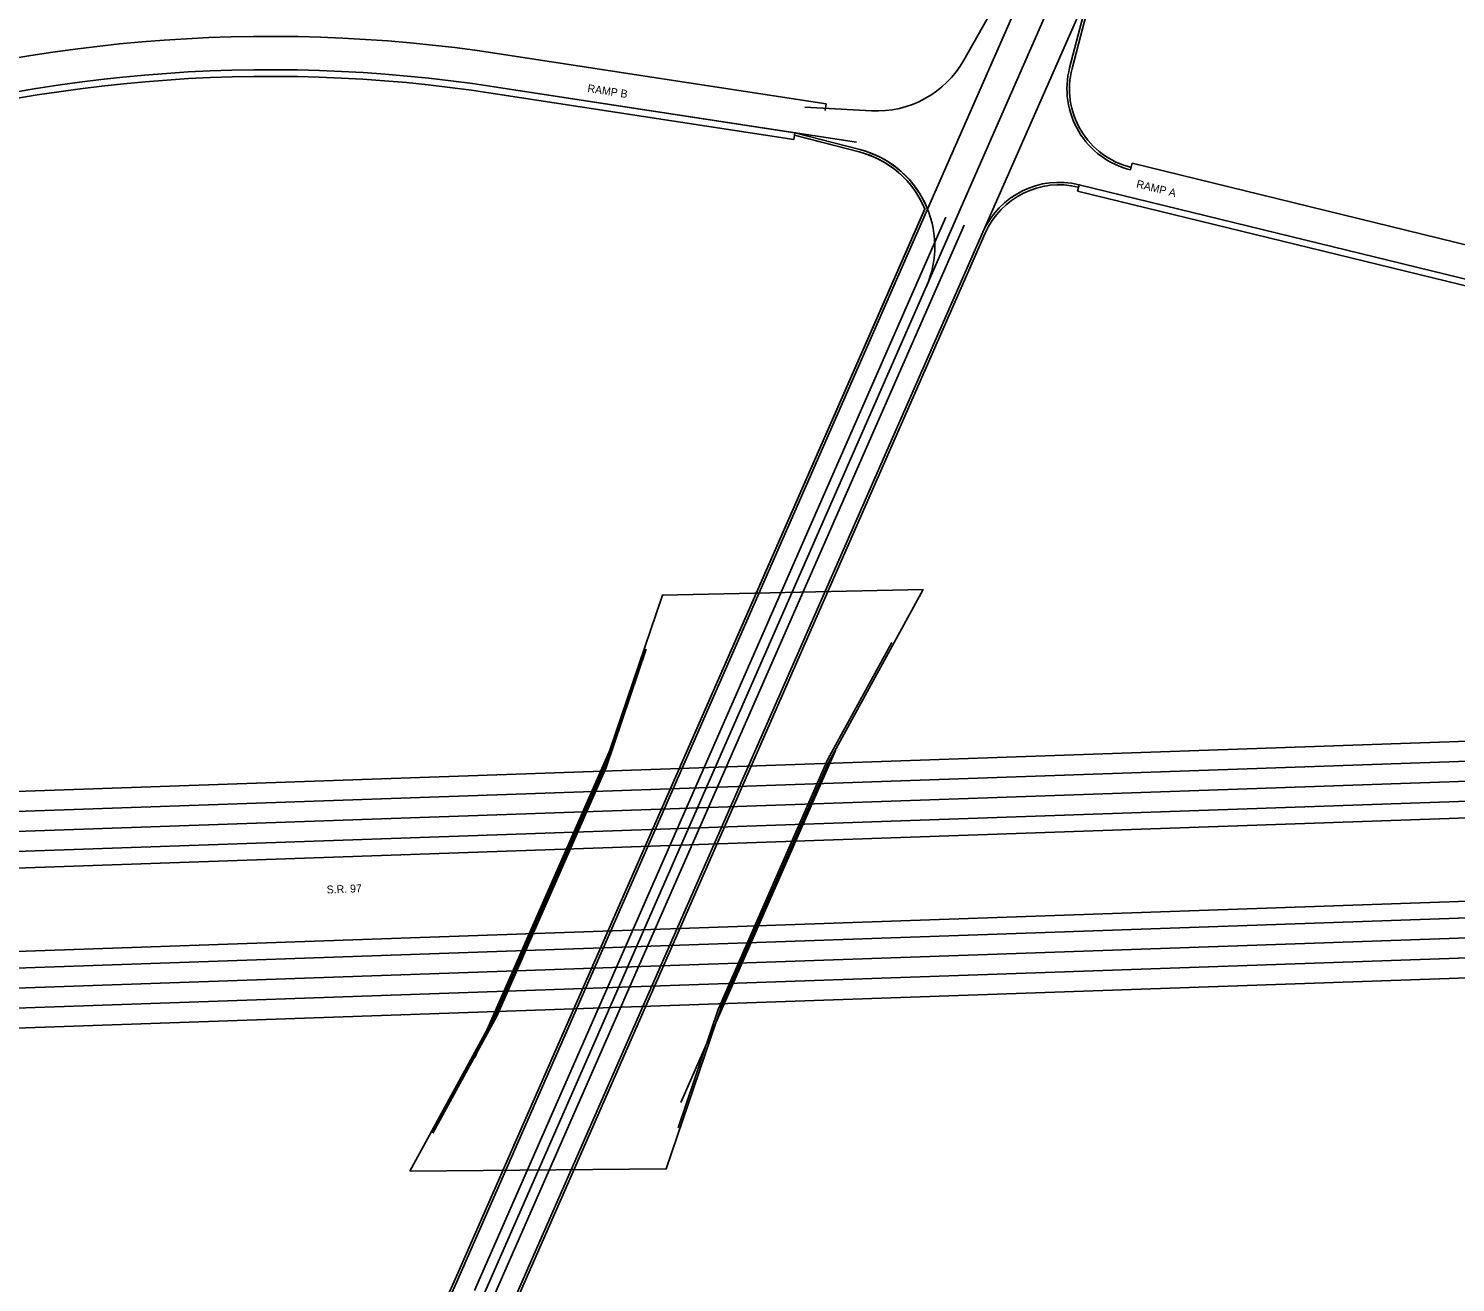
# Model space of a CAD drawing. Extents: x 2315515 to 2326910, y 758186 to 762794.
# Drawn here: x 2320623 to 2321480, y 759999 to 760752 of the extents above; entities that cross this region are included whole.
import ezdxf

# ---------------------------------------------------------------- set-up
doc = ezdxf.new("R2010")
doc.units = 0
for name, color, linetype in [('_CIVIL_CONSTRUCTION', 7, 'Continuous'), ('Bridge_Abutment', 7, 'Continuous'), ('Bridge_Bearing', 7, 'Continuous'), ('Bridge_Deck', 7, 'Continuous'), ('Clipping_Shape', 7, 'Continuous'), ('Default', 7, 'Continuous'), ('Draft_Corr_Design', 7, 'Continuous'), ('Draft_Corr_Range_Design', 7, 'Continuous'), ('E_Terrain_Exterior', 7, 'Continuous'), ('Pavement Marking Yellow', 7, 'Continuous'), ('Road_Curb_Face', 7, 'Continuous'), ('TL_Base Extension Sub', 7, 'Continuous'), ('TL_End Condition Ditch In', 7, 'Continuous'), ('TL_Pavement Centerline', 7, 'Continuous'), ('TL_Pavement Centerline Sub', 7, 'Continuous')]:
    doc.layers.add(name, color=color, linetype=linetype)

msp = doc.modelspace()

# ---------------------------------------------------------------- linework, layer by layer
at = {"layer": '_CIVIL_CONSTRUCTION'}
for p, q in [((2320276.47, 760246.31), (2324005.99, 760375.28)), ((2320278.89, 760176.35), (2324008.41, 760305.32))]:
    msp.add_line(p, q, dxfattribs=at)
at = {"layer": 'Bridge_Abutment'}
for p, q in [((2320969.99, 760308.48), (2320994.04, 760379.52)), ((2321103.18, 760313.34), (2321141.61, 760383.5)), ((2321037.24, 760163.18), (2321103.18, 760313.34)), ((2320904.45, 760159.23), (2320969.99, 760308.48)), ((2320866.02, 760089.07), (2320904.45, 760159.23)), ((2321013.19, 760092.14), (2321037.24, 760163.18))]:
    msp.add_line(p, q, dxfattribs=at)
at = {"layer": 'Bridge_Bearing'}
for p, q in [((2320994.04, 760379.52), (2320969.99, 760308.48)), ((2321141.61, 760383.5), (2321103.18, 760313.34)), ((2321037.24, 760163.18), (2321103.18, 760313.34)), ((2320904.45, 760159.23), (2320969.99, 760308.48)), ((2320866.02, 760089.07), (2320904.45, 760159.23)), ((2321013.19, 760092.14), (2321037.24, 760163.18))]:
    msp.add_line(p, q, dxfattribs=at)
at = {"layer": 'Bridge_Deck'}
for p, q in [((2320891.32, 760134.31), (2320977.73, 760331.08)), ((2321014.91, 760107.35), (2321107.69, 760318.64)), ((2321083.8, 760264.22), (2321104.32, 760310.96)), ((2320946.28, 760259.47), (2320966.81, 760306.21)), ((2320903.45, 760161.93), (2320923.97, 760208.67)), ((2321040.97, 760166.69), (2321061.49, 760213.42))]:
    msp.add_line(p, q, dxfattribs=at)
at = {"layer": 'Clipping_Shape'}
for p, q in [((2320969.05, 760308.84), (2320993.1, 760379.84)), ((2320903.55, 760159.68), (2320969.05, 760308.84)), ((2320865.15, 760089.55), (2320903.55, 760159.68))]:
    msp.add_line(p, q, dxfattribs=at)
msp.add_lwpolyline([(2320852.18, 760066.22), (2320904.32, 760161.43), (2320968.54, 760307.66), (2321003.83, 760411.9), (2321160.28, 760415.23), (2321103.45, 760311.46), (2321039.24, 760165.23), (2321006.16, 760067.57)], close=True, dxfattribs=at)
at = {"layer": 'Default'}
msp.add_line((2320896.62, 759992.18), (2321353.37, 761032.31), dxfattribs=at)
msp.add_line((2320896.62, 759992.18), (2321353.37, 761032.31), dxfattribs=at)
msp.add_line((2320896.62, 759992.18), (2321353.37, 761032.31), dxfattribs=at)
at = {"layer": 'Draft_Corr_Design'}
for p, q in [((2320276.82, 760236.32), (2324006.34, 760365.29)), ((2320278.54, 760186.35), (2324008.07, 760315.32))]:
    msp.add_line(p, q, dxfattribs=at)
at = {"layer": 'Draft_Corr_Range_Design'}
for p, q in [((2320276.06, 760258.31), (2324005.58, 760387.27)), ((2320279.3, 760164.36), (2324008.83, 760293.33))]:
    msp.add_line(p, q, dxfattribs=at)
at = {"layer": 'E_Terrain_Exterior'}
for p, q in [((2321248.25, 760728.26), (2321261.03, 760777.26)), ((2321184.77, 760732.91), (2321204.51, 760767.93)), ((2320902.91, 760716.92), (2321120.26, 760683.63)), ((2320902.91, 760716.92), (2321083.3, 760689.29)), ((2321089.22, 760704.57), (2321129.36, 760702.47)), ((2321083.3, 760689.29), (2321122.24, 760679.28)), ((2321083.3, 760689.29), (2321122.24, 760679.28)), ((2321253.87, 760658.15), (2322014.36, 760472.45)), ((2321253.87, 760658.15), (2322014.36, 760472.45)), ((2320880.14, 759999.42), (2321162.98, 760643.51)), ((2320880.14, 759999.42), (2321162.98, 760643.51)), ((2320913.1, 759984.94), (2321196.22, 760629.68)), ((2320913.1, 759984.94), (2321196.22, 760629.68))]:
    msp.add_line(p, q, dxfattribs=at)
for centre, radius, start, end in [((2321132.5, 760762.38), 60, 267.00289, 330.58171), ((2320768.62, 759840.14), 887, 81.2923, 108.48035), ((2320768.62, 759840.14), 887, 81.2923, 108.48035), ((2321296.63, 760715.64), 50, 165.38258, 256.27773), ((2321107.3, 760621.17), 60, 336.2923, 75.58171), ((2321107.3, 760621.17), 60, 21.8653, 75.58171), ((2321242.01, 760609.57), 50, 76.27773, 156.2923), ((2330052.71, 755971.47), 10018, 156.292302, 157.976797), ((2330052.71, 755971.47), 10018, 156.292302, 157.976797)]:
    msp.add_arc(centre, radius, start, end, dxfattribs=at)
at = {"layer": 'Pavement Marking Yellow'}
for p, q in [((2320891.13, 759994.59), (2321173.97, 760638.69)), ((2320902.12, 759989.77), (2321184.96, 760633.86))]:
    msp.add_line(p, q, dxfattribs=at)
at = {"layer": 'Road_Curb_Face'}
for p, q in [((2321249.7, 760727.88), (2321262.48, 760776.88)), ((2321249.7, 760727.88), (2321262.45, 760776.76)), ((2321082.93, 760687.83), (2321121.86, 760677.82)), ((2321083.08, 760687.8), (2321121.86, 760677.82)), ((2320878.77, 760000.02), (2321161.61, 760644.12)), ((2320878.77, 760000.02), (2321161.35, 760643.53)), ((2320914.48, 759984.34), (2321197.6, 760629.07))]:
    msp.add_line(p, q, dxfattribs=at)
for centre, radius, start, end in [((2321296.63, 760715.64), 48.5, 165.38258, 256.27773), ((2321296.63, 760715.64), 48.5, 165.38258, 256.27773), ((2321107.3, 760621.17), 58.5, 23.80086, 75.58171), ((2321107.3, 760621.17), 58.5, 22.47924, 75.58171), ((2321242.01, 760609.57), 48.5, 76.27773, 156.2923), ((2330052.71, 755971.47), 10019.5, 156.292302, 157.976797), ((2330052.71, 755971.47), 10019.5, 156.292302, 157.976797)]:
    msp.add_arc(centre, radius, start, end, dxfattribs=at)
at = {"layer": 'TL_Base Extension Sub'}
for p, q in [((2320275.64, 760270.3), (2322857.02, 760359.56)), ((2320279.72, 760152.37), (2322571.61, 760231.62))]:
    msp.add_line(p, q, dxfattribs=at)
at = {"layer": 'TL_End Condition Ditch In'}
for p, q in [((2321196.22, 760629.68), (2321261.03, 760777.26)), ((2321162.98, 760643.51), (2321215.5, 760763.1))]:
    msp.add_line(p, q, dxfattribs=at)
at = {"layer": 'TL_Pavement Centerline'}
for p, q in [((2320905.94, 760736.68), (2321102.11, 760706.64)), ((2320905.94, 760736.68), (2321102.11, 760706.64)), ((2320902.31, 760712.96), (2321082.7, 760685.33)), ((2321101.5, 760702.69), (2321102.11, 760706.64)), ((2321083.3, 760689.29), (2321082.7, 760685.33)), ((2321284.77, 760667.07), (2321285.72, 760670.96)), ((2321285.72, 760670.96), (2322019.11, 760491.87)), ((2321253.87, 760658.15), (2321252.92, 760654.26)), ((2321252.92, 760654.26), (2322013.41, 760468.56))]:
    msp.add_line(p, q, dxfattribs=at)
for radius in [907, 907, 883]:
    msp.add_arc((2320768.62, 759840.14), radius, 81.2923, 108.48035, dxfattribs=at)
at = {"layer": 'TL_Pavement Centerline Sub'}
for p, q in [((2320275.23, 760282.29), (2322856.61, 760371.56)), ((2320280.13, 760140.38), (2322560.05, 760219.22))]:
    msp.add_line(p, q, dxfattribs=at)

# ---------------------------------------------------------------- texts
at = {"layer": 'Default'}
for s, rotation, p in [('RAMP B', 351.36386, (2320958.61, 760713.78)), ('RAMP A', 346.28564, (2321287.95, 760656.5)), ('S.R. 97', 2.10743, (2320802.41, 760232.8))]:
    msp.add_text(s, height=4.724, rotation=rotation, dxfattribs=at).set_placement(p)

doc.saveas('drawing.dxf')
